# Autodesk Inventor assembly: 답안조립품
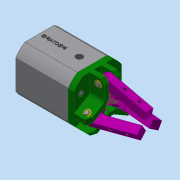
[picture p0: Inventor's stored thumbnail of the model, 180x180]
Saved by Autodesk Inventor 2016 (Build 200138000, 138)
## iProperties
Created: 2020-02
Part Number: 답안조립품
Material: 일반
Document SubType Name: Assembly
Designer: Administrator
Author: Administrator
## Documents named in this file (13)
- C:\Users\Administrator\Desktop\700206V1009\답안조립품.iam
- C:\Users\Administrator\Desktop\700206V1009\본체.ipt
- C:\Users\Administrator\Desktop\700206V1009\E링.ipt
- C:\Users\Administrator\Desktop\700206V1009\O-RING 12x16.ipt
- C:\Users\Administrator\Desktop\700206V1009\O-RING 18x22.ipt
- C:\Users\Administrator\Desktop\700206V1009\O-RING 34x40.ipt
- C:\Users\Administrator\Desktop\700206V1009\로드.ipt
- C:\Users\Administrator\Desktop\700206V1009\본체헤드.ipt
- C:\Users\Administrator\Desktop\700206V1009\볼트 M4.ipt
- C:\Users\Administrator\Desktop\700206V1009\피스톤.ipt
- C:\Users\Administrator\Desktop\700206V1009\핀 A.ipt
- C:\Users\Administrator\Desktop\700206V1009\핀 B.ipt
- C:\Users\Administrator\Desktop\700206V1009\핑거.ipt
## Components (20 placed, 8 different names)
1. E링:1
2. O-RING 12x16:1
3. O-RING 18x22:1
4. O-RING 34x40:1
5. 피스톤:1
6. 핀 A:1
7. 핀 B:1 — 플러쉬:3
8. 핑거:1
9. 핑거:2 — 플러쉬:3
10. 핑거:3 — 플러쉬:1
11. 핀 B:2 — 플러쉬:1
12. 핀 B:3
13. 핀 A:2
14. 핀 A:3
15. O-RING 34x40:2
16. E링:2
17. E링:3
18. E링:4
19. E링:5
20. E링:6
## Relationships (2: Flush 2)
- 플러쉬:1 [Flush]: 핑거:3 ↔ 핀 B:2
- 플러쉬:3 [Flush]: 핀 B:1 ↔ 핑거:2
